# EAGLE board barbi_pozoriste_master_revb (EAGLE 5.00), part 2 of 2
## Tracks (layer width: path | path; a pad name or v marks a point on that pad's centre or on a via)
3.3  (via drill 0.6)
  Top 0.61: v8.89,36.67 9.37,37.15 10.48,37.15 11.11,37.15 11.81,36.45 15.62,36.45 15.83,36.24 Q1.1 15.88,36.32 | v-12.06,32.7 -12.06,27.46 -12.54,26.99 -12.54,21.27 -13.65,20.16 -33.18,20.16 -39.37,13.97 -39.37,-19.21 -35.56,-23.02 -33.02,-23.02 -29.05,-26.99 -28.89,-26.99 -24.45,-31.43 -24.29,-31.43 -20.95,-28.1 -20.95,-26.04 -20.92,-26 JP10.2
  Top 0.813: 10.48,37.15 R24.1
  Bottom 0.61: v8.89,36.67 -8.1,36.67 v-12.06,32.7
5V  (via drill 0.8 pad 1.27)
  Top 0.406: X11.A1 -1.8,-16.69 -7.33,-16.69 -8.58,-15.44 | 0.7,-15.83 1.59,-16.72 7.39,-16.72 X13.A1 9.96,-14.15 9.96,-12.31 11.28,-10.99 13.41,-10.99 X14.A1
  Top 0.61: X12.A1 -8.58,-15.44 | X11.A1 0.7,-14.25 0.7,-15.83 | v-29.63,-15.34 -29.57,-15.41 -17.97,-15.41 -17.77,-15.21 -17.77,-14.12 | -17.77,-14.12 -17.77,-14.09 | X10.A1 -17.77,-14.12
  Bottom 0.406: R65.2 -27.17,-17.71 | R64.2 -27.17,-15.54 | -17.86,-14.21 -17.86,-16.09 -17.28,-16.66 -9.49,-16.66 -8.45,-15.62
  Bottom 0.61: -27.17,-15.54 -27.37,-15.34 | -27.07,-15.34 -27.07,-15.45 R64.2 -27.08,-15.45 | R65.2 -27.07,-17.67 -27.08,-17.67 -27.08,-15.45 | -17.86,-14.21 X10.A1 | X12.A1 -8.45,-14.19 -8.45,-15.62 | -27.08,-15.45 -27.19,-15.34 v-29.63,-15.34
A0  (via drill 0.8 pad 1.27)
  Top 0.305: v-12.18,-22.75 -11.24,-21.81 -11.24,-17.56 -12.11,-16.69
  Top 0.406: -12.11,-16.69 -14.26,-16.69 -15.38,-15.57 -15.38,-14.2 X10.A2
  Bottom 0.406: JP7.1 -5.62,-25.92 | -8.74,-22.79 -8.79,-22.75 v-12.18,-22.75
  Bottom 0.61: -8.74,-22.79 JP7.1
A1
  Bottom 0.254: -0.89,-17.06 -0.89,-22.47
  Bottom 0.406: 2.78,-16.66 -0.45,-16.63 -0.89,-17.06
  Bottom 0.61: X11.A2 3.08,-14.31 3.08,-16.36 2.78,-16.66 | JP7.2 -3.15,-24.23 -0.89,-22.47
A2  (via drill 0.8 pad 1.02)
  Top 0.406: JP7.3 -1.89,-24.57 v-2.34,-21.75
  Bottom 0.254: v-2.34,-21.75 -1.89,-21.3 -1.89,-17.57
  Bottom 0.406: -1.89,-17.57 -2.77,-16.69 -5.18,-16.69 -6.14,-15.73 -6.14,-14.14 X12.A2
  Bottom 0.61: -6.01,-14.19 -6.07,-14.19 X12.A2
A3  (via drill 0.8 pad 1.27)
  Top 0.305: 7.62,-18.17 7.62,-21.38 6.93,-22.06 | 25.03,-22.04 v25.7,-22.71
  Top 0.406: 12.38,-16.02 11.69,-16.71 9.09,-16.71 7.62,-18.17 | 6.87,-22.13 3.8,-22.13 2.09,-23.84 2.09,-25.81 | 6.91,-22.04 25.03,-22.04
  Top 0.61: X13.A2 12.38,-14.23 12.38,-16.02 | 6.87,-22.13 6.93,-22.06 6.91,-22.04 | 2.09,-25.81 1.98,-25.81 JP7.4
  Bottom 0.61: R70.2 26.28,-22.71 v25.7,-22.71
A4  (via drill 0.8 pad 1.27)
  Top 0.305: v15.12,-23.57 | 4.44,-25.83 4.46,-25.83 JP7.5 | 4.7,-23.57 4.44,-23.82
  Top 0.406: v15.12,-23.57 4.7,-23.57 | 4.44,-23.82 4.44,-25.83
  Bottom 0.305: X14.A2 21,-16.09 21,-21.81 19.99,-22.82 15.92,-22.82 15.17,-23.57 v15.12,-23.57
  Bottom 0.406: 4.54,-25.8 4.54,-23.5 5.52,-22.52
  Bottom 0.61: JP7.5 4.54,-25.8 | 6.36,-22.52 6.39,-22.52 | 6.36,-22.52 R71.2 | 5.52,-22.52 6.36,-22.52
A5
  Bottom 0.305: X15.A1 21.77,-15.92 21.77,-22.67 20.66,-23.78 16.55,-23.78 14.89,-25.44 14.89,-26.31 13.77,-27.44 13.77,-27.45 13.7,-27.52 8,-27.52 6.87,-26.43 | 10.45,-22.49 10.45,-22.44 | 10.45,-22.49 R66.2 | 9.79,-24.05 10.45,-23.39 10.45,-22.49
  Bottom 0.406: JP7.6 8.82,-24.05 9.79,-24.05
  Bottom 0.61: JP7.6 7,-25.87 6.87,-25.87 6.87,-26.43
AC_NEUTRAL
  Top 1.676: -51.42,73.42 -51.42,72.97 -26.5,48.05 -11.95,48.05 | -11.95,48.05 -11.95,48.16 X1.B1 | X1.B2 -7.12,48.05 -11.95,48.05 | 63.08,63.54 62.86,63.76 61.51,63.76 55.34,69.94 55.34,70.16 55.22,70.05 | 84.86,-48.49 87.55,-42.65 84.86,-38.16 89.35,-27.84 95.19,-26.94 95.64,-22.9 96.31,-10.1 91.59,-6.73 92.27,5.17 98.55,10.55 94.29,21.11 | 20.58,95.39 25.59,92.95 27.61,91.83 28.96,86.44 40.18,81.95 44.22,85.09 49.39,82.62 | -84.42,49.39 -87.34,42.43 -83.52,39.07 -88.24,28.52 -89.54,27.21 -93.71,27.21 -99.07,21.85 -99.07,6.7 -95.35,2.98 -95.35,-4.3 -98.71,-7.66 -98.71,-18.81 -98.64,-18.88 -98.64,-22.02 -85,-35.67 -85,-38.04 -85.32,-38.16 -90.48,-45.12 -82.62,-56.12 | -48.05,-84.86 -42.66,-87.11 -38.62,-84.41 -28.74,-88.45 -26.05,-94.29 -21.11,-96.09 | 66,55.68 67.12,54.56 68.47,54.56 76.1,62.19 75.79,62.19 X6.B3
  Top 1.778: -84.42,49.39 -80.6,47.82 -72.07,50.97 -72.97,55.01 | -53.66,78.35 -51.87,76.56 -51.42,73.42 -55.46,69.38 -58.83,69.15 | -53.66,78.35 X2.B1 | X2.B3 -64.66,74.99 -58.83,69.15 | X2.B5 -65.78,62.19 -65.34,62.13 | -65.34,62.13 -62.64,61.74 -58.6,65.78 -58.83,69.15 | -72.97,55.01 X2.B7 | -72.97,55.01 -69.15,54.33 -65.11,58.37 -65.34,62.19 -65.34,62.13 | -82.85,-55.9 X3.B1 -82.62,-56.12 -76.11,-49.61 -74.54,-49.84 -69.6,-54.78 -69.6,-57.02 | -69.6,-57.02 X3.B3 | -63.09,-64.88 X3.B5 | -63.09,-64.88 -62.87,-61.51 -67.13,-57.25 -69.6,-57.02 | -56.13,-71.84 X3.B7 | -56.13,-71.84 -56.13,-68.7 -60.17,-64.66 -63.09,-64.88 | -56.13,-71.84 -53.44,-71.39 -47.38,-77.45 -48.05,-84.86 | -21.11,-96.09 14.36,-96.53 45.79,-83.51 52.53,-84.86 54.33,-83.06 X5.B1 54.77,-83.06 49.61,-77.9 49.16,-74.31 52.98,-70.49 56.11,-70.7 | X5.B3 56.35,-70.72 56.11,-70.7 | X5.B5 63.31,-63.76 62.62,-63.72 | 62.62,-63.72 59.49,-63.53 55.67,-67.35 56.12,-70.49 56.11,-70.7 | X5.B7 70.49,-56.57 68.92,-55 | 68.92,-55 62.63,-61.29 62.63,-63.53 62.62,-63.72 | X6.B5 63.08,63.54 62.41,59.27 66,55.68 | X1.B2 -6.78,48.27 | X1.B1 -12.17,47.82 | X6.B1 83.74,46.92 94.29,21.11 | 84.86,-48.49 75.43,-48.94 68.92,-55 | X6.B7 55.34,69.94 55.22,70.05 48.94,76.33 49.39,82.62 | 20.58,95.39 -17.14,95.84 -49.62,81.95 -50.07,81.95 -53.66,78.35
  Bottom 1.676: R89.2 30.46,53.44 36.81,53.44 46.92,63.54 49.61,63.54 61.73,51.41 65.33,51.41 75.65,61.74 75.65,62.19 | 75.65,62.19 | X6.B3 75.65,62.19
AC_PHASE
  Top 1.676: K5.2 42.91,37.46 33.22,47.15 33.22,52.99 31.2,55.01 28.96,55.01 R99.2 | R99.2 | R99.2 | K16.2 16.99,-64.28 29.94,-51.32 C1.1 33.9,-50.78 33.9,-43.33 K1.2 | -48.05,-33.67 -47.83,-33.9 K13.2 -41.99,-34.35 -41.99,-40.18 -28.46,-53.71 K14.2 -28.46,-61.24 | -48.05,-33.67 -61.3,-20.43 -65.78,-20.43 -66.01,-20.2 -66.16,-20.35 K12.2 | C14.1 -33.81,-66.58 -28.46,-61.24 | C13.1 -50.16,-35.78 -48.05,-33.67 | 51.31,31.31 51.86,32.56 | C5.1 51.31,31.31 | 51.31,31.31 64.36,18.26 K4.2 73.53,18.52 75.2,16.84 75.11,16.74 C4.1 75.2,16.52 75.2,9.66 72.51,6.96 72.51,6.06 72.96,5.62 72.96,0.96 K3.2 67.48,-4.62 72.51,-9.65 76.1,-9.65 C3.1 | C3.1 76.55,-9.2 | C3.1 76.46,-13.34 72.96,-16.84 72.51,-16.84 63.89,-25.45 K2.2 63.89,-26.63 70.27,-33 70.24,-33.02 C2.1 | -28.46,-61.24 -28.19,-61.51 -10.78,-61.51 -5.17,-67.12 | -5.17,-67.12 -5.17,-66.98 K15.2 -5.17,-66.89 -5.17,-66.68 -4.72,-66.68 -1.8,-63.76 16.19,-63.76 K16.2 | C15.1 -5.17,-70.77 -5.17,-67.12 | K16.2 17.06,-64.63 17.06,-73.11 C16.1 | C10.1 -68.25,36.66 -68.25,34.58 -62.87,29.19 | -62.87,29.19 -62.82,29.19 K10.2 -62.6,29.41 -52.31,29.41 -38.4,43.33 -37.5,43.33 | -62.87,29.19 -63.09,28.96 -63.09,11.45 -69.6,4.94 -69.6,4.52 | -69.6,4.52 -69.6,4.49 | -69.6,4.52 K11.2 -69.73,4.62 -74.22,9.11 C11.1 | C9.1 -37.72,50.42 -37.72,43.56 -37.5,43.33 | -37.5,43.33 K9.2 -35.57,41.4 | K8.2 -7.7,53.61 -5.58,53.61 -1.7,53.55 -1.7,48.3 -1.91,48.1 -1.98,48.17 X1.B3 | X1.B3 -1.77,48.41 -1.7,48.41 -1.34,48.04 3.07,48.04 3.07,48.15 X1.B4 | X1.B3 -2,48.17 -2,39.45 -2.15,39.3 -26.25,39.3 -26.27,39.31 -33.46,39.31 -35.55,41.4 -35.57,41.4 | -35.57,41.4 -35.62,41.4
  Top 1.778: K11.2 -69.38,4.72
  Top 1.93: K11.2 -69.59,4.72 -69.38,4.72 -62.42,-2.24 -62.42,-16.71 K12.2 -66.17,-20.43 -74.48,-20.43 C12.1
  Bottom 1.676: C3.1 76.64,-9.29 | K3.2 67.32,-4.52 | 10.77,60.62 13.91,60.62 15.94,58.6 20.43,58.6 23.34,55.68 R99.2 | R99.2 28.51,55.45 28.96,55.45 | R99.2 | R99.2 | K7.2 6.28,66.91 | -1.84,48.27 -1.92,48.19 X1.B3 | C5.1 52.08,32.33 50.07,30.32 K5.2 | R99.2 | R99.2 30.53,57.93 K6.2 30.53,60.62 32.78,60.62 C6.1 | K2.2 63.89,-25.45 | C7.1 6.28,70.58 K7.2 | 10.77,60.62 6.28,65.11 K7.2 | K8.2 -18.83,63.31 -18.86,63.31 -18.86,70.52 C8.1 | X1.B4 3,48.22 3,52.84 10.77,60.62
  Bottom 1.778: K12.2 -65.78,-20.43 | K15.2 -5.17,-67.12 | X1.B4 3.1,48.27 | X1.B4 | X1.B4
D2  (via drill 0.8)
  Top 0.61: 2.02,22.45 1.99,22.45 JP4.3 1.96,22.43 | 12.79,12.35 6.04,19.1 4.54,19.1 1.96,21.68 1.96,22.43 | 1.96,22.43 1.96,22.61
  Top 0.813: v12.79,-1.12 12.79,12.35
  Bottom 0.305: SV5.12 27.17,-4.52 23.73,-4.51
  Bottom 0.61: 23.73,-4.51 16.33,-4.61 13.58,-1.91 v12.79,-1.12
D3  (via drill 0.8)
  Top 0.406: -28.55,-2.18 -28.55,-2.23 SV2.12 | -21.62,5.28
  Top 0.813: -28.55,-2.18 -26.78,-1.73 -21.62,3.42 -21.62,5.28 -21.62,8.87 -15.43,15.06 -7.95,15.06 JP4.4 6.23,29.95 6.23,38.57 10.39,42.72 v10.39,43.91
  Bottom 0.406: 12.98,44.02 13.04,44.02 | 12.98,44.02 R55.1 | v10.39,43.91 10.51,44.02 12.98,44.02
  Bottom 1.676: R55.1 12.97,43.96 13.48,44.47 OK1.5
D4  (via drill 0.6)
  Top 0.406: -5.4,-30.8 -5.39,-30.8 C18.2 -5.08,-30.8 -5.11,-30.77 | -3.02,22.54 JP4.5
  Top 0.61: v-24.92,-28.73 -24.92,-28.26 -26.83,-26.35 -26.83,-25.24 -32.38,-19.68 -36.99,-19.68 -37.94,-18.73 -37.94,-18.57 | -5.11,-30.77 U$2.1
  Top 0.813: v-20.48,-33.18 -20.48,-38.1 -15.72,-42.86 -5.4,-42.86 0,-37.78 0,-31.91 -1.11,-30.8 R23.1 -5.08,-30.8 | -37.94,-18.57 -37.94,13.18 -32.23,18.89 -6.67,18.89 JP4.5 | -5.08,-30.8 -5.11,-30.77 | -5.08,-30.8 C18.2
  Bottom 0.406: -3.19,22.41 JP4.5 | -12.35,5.17 -12.38,5.2 SV3.5
  Bottom 0.61: -14.82,10.78 -14.82,7.63 -12.38,5.2
  Bottom 0.813: -14.82,10.78 -3.19,22.41 | v-24.92,-28.73 v-20.48,-33.18
D5
  Bottom 0.305: -12.38,2.89 -12.35,2.92 | -12.38,2.89 SV3.7 | -14.15,2.47 -12.8,2.47 -12.38,2.89
  Bottom 0.406: -5.68,21.71 JP4.6
  Bottom 0.61: -5.68,21.71 -16.39,11 -16.39,4.72 -14.15,2.47
D6  (1 unrouted)
  Bottom 0.305: -28.44,2.84 -28.29,2.7
  Bottom 0.61: JP4.7 -8.18,22.45 -8.09,22.45 -8.09,21.55 -11.68,17.96 -14.37,17.96 -26.05,6.29 -26.27,4.72 -27.62,3.37 -28.52,2.92 -28.52,2.89 SV2.8
D7
  Bottom 0.61: SV2.6 -13.96,19.98 -12.8,19.98 -11.01,21.78 -11.01,22.23 -10.94,22.23 JP4.8
D8
  Bottom 0.406: -28.41,7.97 -28.51,7.97 SV2.4
  Bottom 0.61: JP3.1 -14.82,22.16 -14.82,21.55 -28.29,8.08 -28.72,8.08 | -28.72,8.08 -28.74,8.08 | -28.72,8.08 SV2.4
D9
  Bottom 0.305: -28.56,10.51 SV2.2
  Bottom 0.61: -16.84,22.23 -28.56,10.51
  Bottom 0.813: JP3.2 -17.07,22.45 -16.84,22.23
D10
  Bottom 0.305: JP3.3 -19.81,22.41
  Bottom 0.406: -31.12,10.46 SV2.1 -30.99,10.35 | -30.99,10.35 -30.99,10.33 | -30.99,11.23 -30.99,10.35
  Bottom 0.61: -31.12,10.46 -31.21,10.55 | -19.81,22.41 -30.99,11.23
D11
  Bottom 0.305: JP3.4 -22.19,22.27
  Bottom 0.406: SV2.3 -31.15,7.92 -31.21,7.86 -31.66,7.86
  Bottom 0.61: -22.19,22.27 -33.23,11.23 -33.23,9.43 -31.66,7.86
D12
  Bottom 0.305: JP3.5 -24.73,22.42 -24.7,22.45 -24.7,21.55
  Bottom 0.406: -31.43,5.38 SV2.5
  Bottom 0.61: -24.7,21.55 -34.58,11.68 -34.58,8.53 -31.43,5.38
D13
  Bottom 0.305: -31.1,2.81 -30.99,2.7 | -31.1,2.81 SV2.7 | -31.1,2.81 -31.21,2.92 -31.44,3.15
  Bottom 0.406: -31.21,2.92 -31.13,2.84 SV2.7
  Bottom 0.61: -31.21,2.92 -35.93,7.63 -35.93,12.13 -27.27,20.78 JP3.6 -27.17,22.51
D14
  Top 0.61: R18.1 9.05,26.73 11.45,24.33 11.45,22.6 11.48,22.58 11.46,22.56 JP5.1
  Top 0.813: JP5.1 11.43,22.38 | JP5.1 | JP5.1 11.59,22.54
  Bottom 0.406: JP5.1 11.46,21.15 10.16,19.84 7.62,19.84 -1.91,10.32 -9.68,10.32 -9.84,10.16 -9.85,10.16 SV3.2
D15
  Top 0.406: 21.91,29.65 21.9,35.75 21.9,35.76 19.3,38.35 16.89,38.35 16.81,38.44 | 16.81,38.44 16.76,38.48 | 16.81,38.44 Q1.3
  Top 0.61: 21.91,29.65 21.91,28 20.7,26.8 15.75,26.8 13.97,25.02 13.97,22.48 14,22.45 JP5.2 | R25.2 12.77,38.16 13.34,37.72 16.26,37.72 16.89,38.35 16.83,38.42 Q1.3
  Bottom 0.305: -9.85,7.67 -9.88,7.63 | SV3.4 -9.85,7.67 | -9.85,7.67 -9.66,7.86
  Bottom 0.406: JP5.2 14,19.85 13.02,18.86 8.08,18.86 -2.7,8.08 -9.66,7.86
D16
  Top 0.61: JP1.2 26.06,29.6 26.06,27.97 23.75,25.65 17.02,25.65 16.51,25.15 16.51,22.23 16.54,22.26 JP5.3
  Bottom 0.305: -10.03,5.24 -10.11,5.17 | SV3.6 -10.03,5.24 | -10.03,5.24 -9.43,5.84
  Bottom 0.406: JP5.3 16.54,20.59 13.69,17.74 8.3,17.74 -3.6,5.84 -9.43,5.84
D17
  Top 0.61: JP1.3 28.6,29.89 28.6,28.73 24.38,24.51 19.18,24.51 19.05,24.38 19.05,22.7 19.21,22.54 JP5.4
  Bottom 0.305: -9.66,2.92 -9.4,2.73 SV3.8
  Bottom 0.406: JP5.4 19.31,18.87 17.26,16.82 8.77,16.82 8.75,16.84 -5.17,2.92 -9.66,2.92
D18
  Bottom 0.305: 8.04,1.38 8.08,1.35 | SV4.7 8.04,1.38 | 2.69,9.43 2.91,6.51 8.04,1.38
  Bottom 0.406: JP5.5 21.62,19.39 17.51,15.27 8.75,15.49 2.69,9.43
D19
  Bottom 0.305: SV4.5 8.04,4.08
  Bottom 0.406: JP5.6 24.16,20.13 18.18,14.15 8.75,14.15 3.81,9.21 4.04,8.08 8.04,4.08
D22
  Bottom 0.305: 10.59,9.17 10.55,9.21 | SV4.2 10.59,9.17 | 10.59,9.17 11,8.76
  Bottom 0.406: 11,8.76 17.73,8.76 26.3,17.33 26.38,17.33 28.89,19.84 37.47,19.84 37.62,20 37.66,19.97 JP9.16
D24
  Bottom 0.406: JP9.15 27.8,17.33 16.99,6.51 10.48,6.51 10.47,6.51 | 10.47,6.51 10.32,6.35 | SV4.4 10.47,6.51
D26
  Bottom 0.305: 10.59,4.23 10.55,4.27 | SV4.6 10.59,4.23 | 10.59,4.23 11.22,3.59
  Bottom 0.406: 11.22,3.59 15.71,3.59 26.49,14.82 37.52,14.82 37.62,14.92 37.66,14.89 JP9.14
D28
  Bottom 0.305: SV4.8 16.24,1.43 20.65,5.84 20.65,7.19
  Bottom 0.406: 20.65,7.19 27.16,13.7 34.72,13.7 36.2,12.22 37.62,12.22 37.65,12.25 JP9.13
D30
  Bottom 0.305: SV5.1 25.82,9.21
  Bottom 0.406: 25.82,9.21 25.81,9.22 25.81,10.11 28.28,12.57 33.62,12.57 36.51,9.68 37.69,9.68 | 37.69,9.68 JP9.12 | 37.69,9.68 37.72,9.65
D31
  Bottom 0.406: JP8.12 41.77,9.71 42.86,10.79 42.86,15.56 45.4,18.1 52.23,18.1 52.39,17.94 SV7.1
D32
  Bottom 0.406: 28.34,9.43 28.28,9.43 | SV5.2 28.34,9.43 | 28.34,9.43 34.7,9.43 36.99,7.14 37.62,7.14 37.65,7.17 JP9.11
D33
  Bottom 0.406: SV7.2 54.86,18.03 53.66,16.83 45.88,16.83 43.97,14.92 43.97,9.68 41.43,7.14 40.32,7.14 40.34,7.17 JP8.11
D34
  Bottom 0.254: 30.08,8.08 29.95,8.21 27.13,8.21 25.92,7 25.79,7 25.79,6.94 SV5.3
  Bottom 0.305: SV5.3 25.82,6.97
  Bottom 0.406: 30.08,8.08 33.51,8.08 36.99,4.6 37.62,4.6 37.65,4.63 JP9.10
D35
  Bottom 0.406: SV7.3 46.29,15.49 45.09,14.29 45.09,8.26 41.59,4.76 40.64,4.76 40.36,4.48 | 40.36,4.48 40.32,4.45 | JP8.10 40.36,4.48
D36
  Bottom 0.406: SV5.4 28.37,6.92 28.37,6.96 32.09,6.96 36.99,2.06 37.62,2.06 37.65,2.09 JP9.9
D37
  Bottom 0.406: SV7.4 54.7,15.49 53.5,14.29 46.99,14.29 46.35,13.65 46.35,7.46 40.96,2.06 40.32,2.06 40.34,2.09 JP8.9
D38
  Bottom 0.254: 30,5.53 29.91,5.62 26.6,5.62 25.89,4.91 25.89,4.35 25.84,4.35 SV5.5
  Bottom 0.305: SV5.5 25.92,4.37
  Bottom 0.406: 30,5.53 31.62,5.53 37.62,-0.48 37.65,-0.45 JP9.8
D39
  Bottom 0.406: SV7.5 48.51,12.95 47.47,11.91 47.47,6.03 40.96,-0.48 40.48,-0.48 40.36,-0.6 | 40.36,-0.6 40.32,-0.64 | JP8.8 40.36,-0.6
D40
  Bottom 0.406: JP9.7 37.49,-2.99 37.47,-3.02 30.08,4.37 SV5.6
D41
  Bottom 0.406: SV7.6 55.03,12.8 53.98,11.75 49.53,11.75 48.58,10.79 48.58,3.81 41.75,-3.02 40.32,-3.02 | 40.32,-3.02 40.35,-2.99 JP8.7 | 40.32,-3.02 40.16,-3.17
D42
  Bottom 0.254: SV5.7 25.82,2.01 26.99,3.17 29.69,3.17 30.16,2.7
  Bottom 0.305: SV5.7 25.82,2.03
  Bottom 0.406: JP9.6 37.65,-5.53 37.62,-5.56 30.16,1.91 30.16,2.7
D43
  Bottom 0.406: SV7.7 50.42,10.41 49.85,9.84 49.85,2.86 41.43,-5.56 40.64,-5.56 40.48,-5.4 JP8.6
D44
  Bottom 0.406: SV5.8 28.49,1.83 33.66,-3.33 33.66,-4.13 37.62,-8.1 37.65,-8.07 JP9.5
D45
  Bottom 0.406: JP8.5 41.3,-8.07 50.8,1.43 50.8,8.1 51.59,9.21 53.82,9.21 55.03,10.42 | 55.03,10.42 55.09,10.48 | 55.03,10.42 SV7.8
D46
  Bottom 0.254: JP9.4 38.91,-9.34 42.4,-9.34 43.5,-8.26 44.61,-8.26 44.63,-8.28 44.7,-8.28
  Bottom 0.305: 44.7,-8.28 SV6.1
D47
  Bottom 0.406: JP8.4 43.2,-10.61 44.29,-9.53 53.82,-9.53 55.06,-8.28 | 55.06,-8.28 55.09,-8.26 | 55.06,-8.28 SV6.2
D48
  Bottom 0.254: JP9.3 37.81,-13.15 39.06,-11.87 44.14,-11.87 45.27,-10.77 45.34,-10.77
  Bottom 0.305: SV6.3 52.5,-10.81 52.53,-10.77 45.34,-10.77
D49
  Bottom 0.254: 45.57,-11.9 44.31,-13.15 JP8.3
  Bottom 0.305: SV6.4 55.04,-10.59 55.22,-10.77 53.88,-12.12 45.57,-11.9
D50
  Bottom 0.254: JP9.2 38.92,-14.41 44.8,-14.41 46.02,-13.2 | 46.02,-13.2 46.04,-13.18 | 46.02,-13.2 46.02,-13.24
  Bottom 0.305: SV6.5 52.42,-13.36 52.3,-13.24 46.02,-13.24
D51
  Bottom 0.254: 46.51,-14.59 46.51,-14.61 45.42,-15.69 JP8.2
  Bottom 0.305: SV6.6 55.04,-13.28 55,-13.24 53.65,-14.59 46.51,-14.59 46.47,-14.59
D52
  Bottom 0.254: JP9.1 37.81,-18.23 39.05,-16.97 45.88,-16.94 46.99,-15.88 52.39,-15.88 52.5,-15.98 | 52.5,-15.98 52.55,-16.03 | 52.5,-15.98 SV6.7
D53
  Bottom 0.254: 47.37,-17.29 47.33,-17.29 46.38,-18.23 JP8.1
  Bottom 0.305: 55.22,-15.71 SV6.8 53.65,-17.29 47.37,-17.29
GND  (via drill 0.6, 0.8, 0.9 pad 1.27, 1.3 pad 1.93, 1.4)
  Top 0.305: -13.14,-25.69 -10.12,-22.68 -10.12,-21.29 -10.12,-16.62 -12.73,-14.01
  Top 0.406: 7.85,-6.06 7.91,-6.06 SV4.13 | K13.4 -35.18,-41.01 -35.18,-40.88 -30.86,-40.88 JP10.4 | X10.A3 -12.82,-14.17 -12.82,-14.01 -12.73,-14.01 | -29.86,22.35 -29.86,22.23 | -29.86,22.35 JP3.7 | -29.86,22.68 -29.86,22.35 | C19.1 | C19.1 | C19.1 R22.1 -12.38,-33.81 -12.06,-33.5 -12.06,-32.86 -11.27,-32.07 -10.32,-32.07 -9.68,-31.43 -9.68,-30.96 | -9.68,-30.96 | -9.68,-30.96 U$2.2 -9.75,-30.77 -9.78,-30.73 -9.78,-29.08 | U$1.1 1.97,-30.29 0,-28.32 -9.02,-28.32 -9.78,-29.08 | JP10.5 -13.3,-26.2 -11.05,-28.45 -10.41,-28.45 -9.78,-29.08 | 15.24,30.99 | JP2.1 15.24,30.99 | R19.2 15.21,30.96 15.24,30.99 | -10.12,-21.29
  Top 0.61: v-22.78,-10.73 -22.55,-11.75 -12.54,-11.75 | -12.54,-11.75 -12.39,-11.75 -12.37,-11.72 -12.34,-11.72 -12.34,-4.96 SV3.13 | -13.14,-25.69 JP10.5 | -12.54,-11.75 | -12.54,-11.75 -12.54,-14 | 7.46,-6.78 SV4.13 7.46,-6.78 | 7.46,-6.78 7.46,-12.24 5.88,-13.82 5.88,-14.01 X11.A3 | 7.46,-6.78 7.46,-7.97 7.47,-7.96 24.4,-7.96 | 25.94,-5.67 25.94,-5.65 | 25.94,-5.67 SV5.13 | 24.4,-7.96 25.94,-6.42 25.94,-5.67 | X15.A2 26,-14.19 26,-9.55 24.4,-7.96 | K3.4 65.81,5.64 63.34,3.17 63.34,-11.91 67.64,-16.2 K2.4 | 48.94,-29.63 48.94,-29.64 48.9,-29.69 52.32,-33.11 LSP3.MP | K12.4 -64.78,-29.83 -68.74,-25.88 v-68.74,-22.86 | -59.05,0.25 -58.98,0.25
  Top 0.813: SV6.13 52.64,-23.66 | 48.94,-29.63 44.45,-29.63 K1.4 | SV7.13 49.5,-0.2 49.5,-22.11 50.96,-23.57 52.53,-23.57 | K9.4 -40.67,32.13 -39.29,30.76 -37.95,30.76 -29.86,22.68 | K15.4 5.16,-67.06 5.16,-72.06 | 5.16,-72.06 10.32,-77.23 18.85,-77.23 26.49,-69.59 26.49,-60.61 26.42,-60.61 K16.4 | LSP2.MP -12.58,-68.22 -12.58,-72.29 -14.37,-74.08 -14.37,-76.33 -11.01,-79.7 -2.48,-79.7 5.16,-72.06 | v77.48,18.69 77.4,18.69 68.69,27.39 61.96,27.39 61.28,28.07 61.14,27.92 K4.4
  Top 1.016: LSP7.MP -58.98,0.25 -58.96,2.06 v-63.09,6.06 | K4.4 43.25,45.8 v38.16,45.8 | K7.4 -3.6,66.83 -3.6,63.54 | -3.6,63.54 -3.6,61.07 -0.23,57.7 -0.23,57.25 LSP5.MP 3.59,57.48 13.91,47.15 17.06,47.15 OK1.4 | -3.6,63.54 | -3.6,63.54 v12.34,63.54 | v-41.4,0.25 -59.05,0.25 | LSP1.MP -20.79,-3.9 -22.61,-5.71 -22.61,-10.67 -22.73,-10.79 -22.78,-10.75 v-22.78,-10.73
  Top 1.27: v-29,36.47 -36.33,36.47 -38.89,33.91 -40.67,32.13 | K8.4 -28.1,57.34 -25.14,54.38 -21.97,54.38 -22.01,54.34 LSP6.MP
  Top 1.422: -40.67,32.13 | -38.89,33.91
  Bottom 0.305: 7.92,-15.75 7.92,-22.18
  Bottom 0.406: SV2.13 -31.1,-4.82 | 6.33,-14.17 7.92,-15.75 | JP10.5 -13.33,-25.83 -13.33,-25.72 -15.7,-25.72 JP10.4 | R70.1 34.21,-18.33 36.67,-20.8 37.31,-20.8 37.47,-20.64 37.49,-20.66 JP11.1 37.44,-20.77 | 37.44,-20.77 JP11.2 | 37.44,-20.77 37.31,-20.64 | 23.57,32.38 23.57,32.43 22.73,33.27 17.53,33.27 15.24,30.99 | 23.57,32.38 JP1.1 | 15.24,30.99 | 15.24,30.99 JP2.1 | 23.57,32.38 23.62,32.38 25.11,33.87 25.11,35.11
  Bottom 0.61: -36.05,-13.1 -35.99,-13.1 S1.1 -35.85,-13.06 -29.53,-13.06 S1.2 -29.31,-13.02 -27.53,-13.02 LED33.C -26.86,-13.48 -26.86,-11.87 -26.13,-11.14 -25.52,-10.62 -23.71,-10.65 v-22.78,-10.73 | -31.18,-4.63 -31.18,-4.7 SV2.13 | 7.92,-22.18 R71.1 | X11.A3 5.69,-14.2 5.69,-14.17 6.33,-14.17 | 25.98,-14.21 25.98,-14.17 | X15.A2 25.98,-14.21 | R70.1 25.98,-15.55 25.98,-14.21 | JP11.2 48.24,-20.77 51.12,-23.65 52.55,-23.65 52.68,-23.52 | 52.68,-23.52 52.7,-23.5 | 52.68,-23.52 SV6.13 | SV7.13 52.49,1.64 56.52,-2.38 56.52,-5.08 67.64,-16.2 K2.4 | OK1.4 18.55,47.01 19.84,45.72 19.84,41.91 23.81,37.94 23.81,37.47 25.11,36.17 | 25.11,36.17 C99.- | 25.11,36.17 25.11,35.11 | v-68.74,-22.86 -68.74,-20 -66.2,-17.46 -66.04,-17.46 -59.05,-10.48 -59.05,-8.26 -59.05,-8.1 LSP7.MP | -29.84,22.35 -29.81,22.39 JP3.7
  Bottom 0.813: v-63.09,6.06 -63.32,6.29 -63.32,16.62 -66.68,19.98 -66.66,19.98 K10.4 | K3.4 71.43,5.64 75.46,1.62 75.68,1.62 80.56,6.5 80.56,15.61 v77.48,18.69
  Bottom 1.016: C99.- 25.6,35.81 28.06,35.81 | 28.06,35.81 34.01,35.81 35.8,37.61 35.8,37.58 K5.4 | -36.05,-11.3 -36.05,-13.1 | -36.05,-11.3 -31.18,-6.43 -31.18,-4.7 | v38.16,45.8 33.67,45.8 28.06,40.19 28.06,35.81 | K7.4 -16.66,54.33 LSP6.MP | K6.4 20.11,63.54 v12.34,63.54 | -36.05,-11.3 -36.05,-2.3 -38.61,0.25 | -38.61,0.25 -38.61,11.94 -29.84,20.7 -29.84,22.35 | -38.61,0.25 v-41.4,0.25 | LSP7.MP -59.05,-8.26 -61.77,-5.54 K11.4
  Bottom 1.27: v-29,36.47 -23.12,42.35 -23.12,53.34 -22.03,54.44 -22.01,54.42 LSP6.MP
  pour Bottom (isolate 1.676, hatched): -47.38,46.03 -49.4,14.82 arc-90 44,16.62 60.84,31.66 arc-90 50.96,-50.06 arc-90 -50.07,-50.06 -52.31,-47.82 arc-90 -52.99,43.56 -48.5,46.7 arc-90
  pour Top (isolate 1.422, hatched): -47.6,46.25 -49.4,14.82 arc-90 43.77,16.39 61.06,31.88 arc-90 49.84,-50.29 arc-90 -51.19,-50.29 -53.44,-48.04 arc-90 -53.44,42.66 -49.62,46.48 arc-90
INPUT1
  Bottom 0.61: 37.96,-39.73 37.97,-39.75 | R119.1 37.96,-39.73 | 32.32,-38.84 37.06,-38.84 37.96,-39.73
  Bottom 0.813: SV1.2 -52.54,5.98 -52.54,-0.22 -45.24,-7.07 -45.24,-15.6 -36.6,-24.24 -36.6,-32.55 -9.1,-60.05 9.98,-60.05 31.2,-38.84 32.32,-38.84 | R119.1 37.9,-39.73
INPUT2
  Bottom 0.61: 67.18,-24.13 67.19,-24.14 67.23,-24.14 | 66.34,-24.13 67.18,-24.13 | R112.1 68.42,-22.9 67.18,-24.13
  Bottom 0.813: SV1.1 -43.67,1.64 -43.67,-14.93 -35.25,-23.35 | -8.54,-57.92 9.42,-57.92 30.53,-36.82 33.67,-36.82 37.04,-33.45 37.04,-30.31 39.28,-28.06 55.22,-28.06 60.39,-22.9 65.1,-22.9 66.34,-24.13 | -8.54,-57.92 -8.76,-57.92 | 67.23,-24.14 67.23,-24.13 | -35.25,-23.35 | -35.25,-23.35 -25.37,-33.23 -25.37,-41.08 -8.54,-57.92
INPUT3
  Bottom 0.305: SV1.4 -50.23,8.2 -44.79,8.2
  Bottom 0.406: -44.79,8.2 -39.29,13.7 -39.29,19.31 -32.78,25.82 39.45,25.82 42.37,22.9
  Bottom 0.61: 42.46,22.9 42.37,22.9 43.55,22.9 43.66,23.01 59.15,23.01 62.97,19.2 62.97,16.28 64.65,14.6 64.65,1.13 66.17,-0.38 69.98,-0.38 70.01,-0.35 70.01,-0.32
  Bottom 0.813: R113.1 69.95,1.49 70.01,1.43 70.01,-0.32
INPUT4
  Bottom 0.406: -48.92,9.43 -46.03,9.43 -40.64,14.82 -40.64,19.31 -33.79,26.16 -33.81,26.17 | 45.54,24.7 43.3,26.94 -32.78,26.94 -32.8,26.92 -33.04,26.92 -33.79,26.17 -33.81,26.17 | -33.81,26.17 -33.82,26.17
  Bottom 0.61: 45.54,24.7 60.27,24.7 61.47,23.5 63.12,23.5 64.9,25.27 64.88,25.29 R114.1
  Bottom 0.813: -48.92,9.43 SV1.3 | 64.77,25.08 64.86,25.18 R114.1
INPUT5
  Bottom 0.305: SV1.6 -50.27,10.78 -46.7,10.78
  Bottom 0.406: -41.76,15.72 | -41.76,15.72 -46.7,10.78 | -41.76,15.72 -41.76,19.76 -33.23,28.29 37.94,28.29 40.13,30.48 40.13,36.58 40.16,36.54 R115.1
INPUT6  (via drill 0.8)
  Top 0.61: v26.94,60.84 26.71,60.4 26.49,60.62 4.04,60.62 v3.92,60.73
  Bottom 0.406: -48.97,12.01 -47.26,12.01 -43.11,16.17 -43.11,20.21 -34.13,29.19 -30.81,29.19 -16.66,43.33 -16.66,48.74 -4.72,60.84
  Bottom 0.61: -48.97,12.01 SV1.5 | v3.92,60.73 3.81,60.84 -4.72,60.84
  Bottom 0.813: R116.1 26.19,64.93 26.94,64.19 v26.94,60.84
INPUT7
  Bottom 0.305: SV1.8 -50.31,13.36 -47.71,13.36
  Bottom 0.406: -2.48,64.77 -2.48,64.89 -17.78,49.42 -17.78,44.01 -31.48,30.31 -34.58,30.31 -44.12,20.77 -44.34,16.5 -47.47,13.38 -47.71,13.38 -47.71,13.36 | -2.48,64.77
  Bottom 0.61: -2.81,64.77 -2.48,64.77 0.89,64.77 1.65,65.53 1.65,68.07 0.14,69.58 | 0.14,69.58 0.13,69.6 | 0.14,69.58 R117.1
INPUT8
  Bottom 0.61: -49.17,14.6 SV1.7 -48.72,14.6 -46.48,16.84 -46.72,23.36 -27.86,42.22 -27.62,55.9 -27.62,55.95 -23.24,60.33 -23.24,61.72 -24.66,63.14 R118.1
INPUT9
  Bottom 0.813: SV8.2 -57.25,1.51 -57.25,26.27 -57.17,26.27 -43.94,39.5 -42.55,39.5 -41.77,38.72 R91.1 -41.77,38.59 -41.75,38.58
INPUT10
  Bottom 0.61: SV8.1 -59.05,0.76 -59.05,24.02 -61.97,26.94 -64.21,26.94 -64.24,26.94 -64.26,26.92 -65.15,26.92 -67.46,24.61 R101.1
INPUT11  (1 unrouted)
  Bottom 0.305: -52.76,-7.86 -52.54,-8.08 -49.84,-8.08 -48.95,-8.98 SV8.4 -48.95,-9.43
  Bottom 0.61: -52.76,-7.86 -62.42,1.8 | R111.1 -71.62,-1.07 | -71.4,-0.75 -71.4,0.61 -70.23,1.78 -62.36,1.78 -62.38,1.76
  Bottom 0.813: R111.1 -71.85,-1.2 -71.4,-0.75
INPUT12
  Bottom 0.61: R121.1 -65.9,-27.06 -67.13,-25.83 -67.13,-24.94
  Bottom 0.813: SV8.3 -51.57,-9.43 -52.54,-9.43 -67.13,-24.02 -67.13,-24.94
  Bottom 1.016: R121.1 -65.86,-27.09
INPUT13  (via drill 0.8)
  Top 0.813: SV8.6 -48.93,-11.9 -45.58,-15.23 -39.29,-21.52 v-39.29,-37.04
  Bottom 0.813: v-39.29,-37.04 -39.32,-37.04 -39.37,-36.99 -39.74,-37.36 R131.1
INPUT14  (via drill 0.8)
  Top 0.813: v-62.19,-23.57 -54.34,-31.43 -54.34,-35.92 -35.93,-54.33 v-33.68,-54.33
  Bottom 0.813: SV8.5 -62.19,-22.59 v-62.19,-23.57 | v-33.68,-54.33 -30.99,-54.33 -26.27,-59.04 -26.27,-62.63 -26.95,-64.23 -26.26,-64.55 -25.52,-64.81 -25.45,-64.81 R141.1
INPUT15  (via drill 0.8)
  Top 0.813: v-5.17,-63.98 -5.17,-62.19 -9.66,-57.7 -11.01,-57.7 v-12.46,-59.16
  Bottom 0.813: v-5.17,-63.98 -2.7,-66.45 -2.7,-69.26 0.68,-69.26 0.79,-69.37 0.8,-69.37 151.1 | SV8.8 -38.71,-24.66 -38.71,-32.47 -12.54,-58.64 -12.54,-59.14 -12.48,-59.14 v-12.46,-59.16
  Bottom 1.016: 1.12,-69.37 | 151.1 1.12,-69.37 | 1.12,-69.37 1.08,-69.33
INPUT16
  Bottom 0.813: SV8.7 -58.6,-21.53 -58.6,-24.02 -55.23,-27.39 -45.92,-27.27 -27.62,-45.57 | -27.62,-45.8 -27.84,-54.78 -20.43,-62.19 18.63,-62.19 19.75,-63.31 19.75,-65.11 20.43,-65.78 | -27.62,-45.8 -27.62,-45.57 | 20.43,-65.78 20.43,-65.93 | -27.62,-45.8 -27.62,-45.57 | -27.62,-45.8 | R161.1 22.84,-64.71 22.08,-65.47 22.08,-65.42 22.07,-65.41 21.69,-65.78 20.43,-65.78
LAMP1
  Bottom 1.676: F1.1 57.69,-48.72 53.2,-48.72 L1.2
LAMP2
  Bottom 1.676: F2.1 90.47,-22.8 90.47,-22.67 84.33,-22.67 L2.2
LAMP3
  Bottom 1.676: 83.8,-10.1 83.74,-10.1 | L3.2 83.8,-10.1 | F3.1 88.41,-10.1 83.8,-10.1
LAMP4
  Bottom 1.676: 81.57,18.26 81.49,18.19 | L4.2 81.57,18.26 | F4.1 82.79,19.48 81.57,18.26
LAMP5
  Bottom 1.676: 47.47,57.36 47.59,57.48 | 47.47,57.36 F5.1 | L5.2 45.15,55.04 47.47,57.36
LAMP6
  Bottom 1.676: F6.1 23.6,88.26 23.57,88.23 23.57,80.89 25.19,79.26 25.11,79.17 L6.2
LAMP7
  Bottom 1.676: -9.66,90.37 -9.66,90.48 | -9.66,90.37 F7.1 | -5.39,82.17 -9.66,86.44 -9.66,90.37
  Bottom 1.778: L7.2 -5.39,82.17
LAMP8
  Bottom 1.676: -35.54,73.26 -35.48,73.19 | -35.54,73.26 L8.2 | F8.1 -40.79,78.51 -35.54,73.26
  Bottom 1.778: L8.2 -35.7,73.42
LAMP9
  Bottom 1.676: F9.1 -53.56,45.48 L9.2
LAMP10
  Bottom 1.676: -81.5,24.47 -81.49,24.46 L10.2 -81.55,24.25 -88.46,24.25 -90.03,22.68
  Bottom 1.778: -90.03,22.68 F10.1
LAMP11
  Bottom 1.676: L11.2 -85.17,-7.33 -85.09,-7.41 -87.07,-9.38 F11.1
  Bottom 1.778: L11.2 -85.09,-7.41
LAMP12
  Bottom 1.676: L12.2 -76.17,-37.44 -76.11,-37.49 -80.62,-42 F12.1
LAMP13
  Bottom 1.676: L13.2 -56.58,-39.96 -62.07,-45.45 F13.1
LAMP14
  Bottom 1.676: L14.2 -40.13,-73.86 -40.19,-73.86 -40.19,-78.16 F14.1
LAMP15
  Bottom 1.676: F15.1 -12.8,-90.51 -12.8,-84.19 -11.23,-82.62
  Bottom 1.778: L15.2 -11.23,-82.62
LAMP16
  Bottom 1.676: F16.1 19.52,-88.23 19.53,-88.23 19.53,-83.74 16.83,-81.04
  Bottom 1.778: L16.2 16.83,-81.04
N$1
  Bottom 1.676: K2.1 62.16,-30.29 62.18,-30.31 59.49,-33 59.49,-36.59 64.65,-41.76 70.74,-41.76 73.5,-38.99 | L2.1 76.3,-36.2 73.5,-38.99 | R2.2 73.5,-38.99
N$2
  Bottom 1.676: K1.1 29.18,-45.8 29.18,-50.74 35.69,-57.25 L1.1 38.39,-52.31 48.71,-41.98 52.75,-41.98 R1.1
N$3
  Bottom 1.676: C1.2 45.03,-34.44 R1.2
N$4
  Bottom 1.676: R2.1 63.82,-33.61 64.14,-33.61 64.2,-33.67 75.98,-21.9 75.98,-19.21 | 75.98,-19.21 76.1,-19.08 | 75.98,-19.21 C2.2
N$5
  Bottom 1.676: 86.47,37.5 90.27,34.85 99.37,9.66 94.5,7.15 94.39,-6 99.57,-9.56 98.56,-19.91 | 98.56,-19.91 98.33,-24.47 | 98.56,-19.91 98.78,-23.35 95.69,-30.05 90.3,-30.07 86.54,-39.22 90.56,-43.4 84.63,-52.27 79.52,-58.56 X5.B8
  Bottom 1.778: 86.47,37.5 F4.2 | X5.B8 79.69,-58.59
N$6
  Bottom 1.676: 83.65,6.42 83.51,6.29 83.27,6.53 R3.2 | K3.1 67.52,-9.6 67.57,-9.65 83.65,6.42 | 83.65,6.42 L3.1
N$7
  Bottom 1.016: OK1.1 24.52,41.93 24.47,41.98 23.12,41.98 22,43.11 22,48.95 21.32,49.62 15.94,49.62 13.91,51.64 13.91,53.88 15.71,55.68 | 15.71,55.68 | 15.71,55.68 R99.1
  Bottom 1.676: 24.91,41.98 24.86,41.93 OK1.1
N$8
  Bottom 1.676: C3.2 71.67,10.5 R3.1
N$9
  Bottom 1.778: F1.2 43.55,-64.66 X5.B2
N$10
  Bottom 1.676: 72.73,-44.45 72.6,-44.45 58.37,-58.68 58.37,-65.59 65.33,-72.54 | 65.33,-72.54 65.34,-72.56 | 65.33,-72.54 X5.B4
  Bottom 1.778: 81.94,-43.33 F2.2 81.72,-43.55 72.73,-44.45
N$11
  Bottom 1.676: C4.2 69.22,30.46 67.27,32.41 R4.1
N$12
  Bottom 1.676: R4.2 72.37,36.29 75.2,33.45 75.27,33.52 L4.1 75.29,33.54 75.43,33.68 75.65,33.45 75.65,23.57 66.97,14.9 K4.1
N$13
  Bottom 1.676: R5.2 40.35,48.55 52.53,36.37 56.12,36.37 56.57,36.82 56.63,36.76 L5.1 56.83,36.63 56.35,36.15 56.35,32.56 50.52,26.73 K5.1
N$14
  Bottom 1.27: 29.45,45.58 29.46,45.59 | 29.45,45.58 29.41,45.58 | OK1.2 28.33,44.46 29.45,45.58
  Bottom 1.676: R89.1 24.91,52.31 29.41,47.82 29.41,45.58 | OK1.2
N$15
  Bottom 1.676: R5.1 31.58,39.67 33.22,41.31 39.51,41.31 41.3,43.11 C5.2
N$16
  Bottom 1.676: 90.92,10.11 90.92,-7.41 96.31,-11 95.97,-15.6 94.96,-24.02 93.61,-26.96 87.78,-26.71 83.29,-37.94 82.66,-39.62 86.91,-43.93 83.61,-48.35 80.93,-47.93 76.33,-48.04 75.03,-48.04 67.48,-55.59 67.48,-60.44 72.47,-65.44 72.43,-65.47 X5.B6
  Bottom 1.778: 90.92,10.11 F3.2
N$17
  Top 0.61: 35.24,58.76 K6.1 | 31.88,64.21 31.88,64.33
  Top 1.676: R6.2 18.98,67.58 28.51,67.58 31.88,64.21 35.24,60.84 35.24,58.76 | 31.88,64.33 L6.1
N$18
  Bottom 1.676: 24.67,71.83 24.69,71.84 24.43,71.84 C6.2 24.41,71.87 24.46,71.92 22.22,74.16 R6.1
N$19
  Bottom 1.778: F5.2 71.84,51.19 79.47,58.82 X6.B2
N$20
  Bottom 1.676: F8.2 -12.74,96.67 -1.1,96.08 | 20.62,98.01 31.65,93.62 32.1,90.03 40.41,86.66 44.22,88.68 54.1,83.74 56.8,81.05
  Bottom 1.778: -1.1,96.08 14.48,95.9 20.62,98.01 | 56.8,81.05 X6.B8
N$21
  Bottom 1.676: C7.2 -4.15,75.21 -6.32,75.21 R7.1
N$22
  Top 1.676: R7.2 -7.19,67.16 -7.19,70.5 -6.74,70.95 6.28,70.95 | 6.28,70.95 8.08,70.95 11.22,67.8 11.22,66.97 | 11.22,66.97 11.22,66.91 | 11.22,66.97 K7.1 | L7.1 6.06,76.78 6.06,71.62 6.28,71.39 6.28,70.95
N$23
  Top 1.676: R8.2 -30.31,59.25 -30.31,62.19 -27.62,64.89 -23.13,66.46 -22.79,66.79 | -22.79,66.79 -22.23,67.35 -21.11,78.78 L8.1 | -22.79,66.79 -22.68,66.68 -15.56,66.68 K8.1
N$24
  Bottom 1.676: C8.2 -30.99,66.5 -30.99,66.46 -33.66,66.46 R8.1
N$25
  Bottom 1.676: 22,93.85 28.06,91.83 29.41,86.44 40.41,81.72 44.9,84.87 50.78,81.87 49.14,74.73 56.53,67.34 59.81,67.34 61.92,69.44 61.92,69.66 65.1,72.84 65.22,72.84 | 65.22,72.84 65.24,72.84 | 65.22,72.84 X6.B6
  Bottom 1.778: F7.2 17.51,92.05 22,93.85
N$26
  Bottom 1.676: F6.2 44.51,73.76 58.39,59.88 66.32,59.88 72.13,65.68 72.16,65.66 X6.B4
N$27
  Bottom 1.016: R112.2 68.47,-18.63 67.12,-18.63 66.9,-18.41 66.81,-18.5 K2.3
N$28
  Bottom 1.016: K3.3 67.39,3.1 67.35,3.15 67.62,3.42 R113.2
N$29
  Bottom 1.016: K4.3 61.99,25.56 61.96,25.6 63.41,27.04 R114.2
N$30
  Bottom 0.813: K5.3 37.49,35.74 37.49,36.6 38.83,37.94 38.83,37.87 R115.2
N$31
  Bottom 0.813: K6.3 23.34,63.76 23.34,64.55 R116.2
N$32
  Bottom 0.813: K7.3 -1.34,67.34 -1.76,67.76 R117.2
N$33
  Bottom 0.813: R118.2 | R118.2 | K8.3 -25.75,61.67 R118.2
N$34
  Bottom 1.016: R119.2 39.28,-37.94 K1.3
N$36
  Bottom 1.016: R101.2 -67.96,22.61 -66.46,22 -66.01,22 -65.75,22.26 K10.3
N$38
  Bottom 0.305: R111.2 -71.85,-3.14 -69.83,-3.14 K11.3
N$40
  Bottom 1.016: K12.3 -63.22,-27.49 -63.09,-27.61 -63.85,-28.37 R121.2
N$42
  Bottom 0.813: R131.2 -37.05,-39.73 K13.3
N$44
  Bottom 0.813: R141.2 -21.84,-66.28 -22.01,-66 -21.33,-63.98 -21.36,-64.01 K14.3
N$46
  Bottom 1.016: K15.3 2.5,-67.09 2.46,-67.12 2.83,-67.5 151.2
N$48
  Bottom 0.813: K16.3 24.03,-61.75 25.36,-63.08 R161.2
N$50
  Bottom 1.016: R91.2 -41.31,35.47 K9.3
N$59
  Bottom 1.676: R9.1 -44.39,30.09 -42.84,30.31 -31.62,41.53 -31.62,44.52 -31.92,44.82 -31.89,44.85 K9.1 -31.89,45.22 -31.84,45.26 -31.88,45.3 -31.88,49.11 -39.12,56.35 L9.1
N$60
  Bottom 1.676: R9.2 -52.87,38.39 -49.62,38.39 -48.27,39.74 -48.27,39.87 C9.2
N$61
  Bottom 1.676: K10.1 -60.62,34.13 -67.81,41.31 -73.19,41.31 -74.94,39.57 L10.1 -75.22,39.52 -75.22,32.56 -71.4,28.74 -71.4,18.98 R10.2
N$62
  Bottom 1.676: R10.1 -79.56,20.29 -79.48,20.21 -76.56,23.13 -74.3,23.13 C10.2
N$63
  Bottom 1.676: R11.2 -70.11,-9.82 -77.46,-2.47 -77.46,2.02 | L11.1 -77.81,2.02 -77.46,2.02 | K11.1 -69.88,9.88 -70.05,9.88 -70.05,9.43 -77.46,2.02
N$64
  Bottom 1.676: -79.92,-9.86 -79.93,-9.88 | -79.92,-9.86 R11.1 | C11.2 -78.45,-8.4 -79.92,-9.86
N$65
  Bottom 1.676: -69.64,-33.26 -69.6,-33.23 | C12.2 -69.64,-33.26 | R12.1 -71,-34.62 -69.64,-33.26
N$66
  Bottom 1.676: R12.2 -64.31,-34.03 -71.4,-26.94 | -82.48,-22.14 L12.1 -77.45,-27.16 -71.62,-27.16 -71.4,-26.94 | K12.1 -68.1,-16.01 -71.4,-19.3 -71.4,-26.94
N$67
  Bottom 1.676: K13.1 -46.48,-29.86 -50.52,-29.86 -55.01,-34.35 -55.01,-37.49 -44.68,-47.82 L13.1 -43.78,-52.76 R13.2
N$68
  Bottom 1.676: C13.2 -34.27,-46.38 R13.1
N$69
  Bottom 1.676: K14.1 -31.89,-60.42 -31.89,-73.19 -24.93,-80.15 | -24.93,-80.15 -24.91,-80.15 L14.1 | R14.2 -23.34,-80.15 -24.93,-80.15
N$70
  Bottom 1.676: C14.2 -22.22,-72.06 -17.29,-72.06 -16.17,-70.94 -16.01,-70.94 R14.1
  Bottom 1.778: R14.1 -15.95,-70.72
N$71
  Bottom 1.676: 9.42,-70.69 9.42,-70.49 | R15.1 9.42,-70.69 | 4.93,-75.88 9.42,-71.39 9.42,-70.69
  Bottom 1.778: 4.93,-75.88 C15.2
N$72
  Bottom 1.676: 5.16,-82.83 5.16,-82.84 | 5.16,-82.83 L15.1 5.37,-82.62 8.65,-82.62 R15.2 | K15.1 5.16,-82.3 5.16,-82.83
N$73
  Bottom 1.676: K16.1 15.84,-70.04 20.65,-70.04 25.36,-74.76 32.1,-74.76 32.1,-74.71 L16.1 | 31.88,-74.53 31.92,-74.53 L16.1 | R16.2 37.05,-74.31 32.1,-74.31 32.1,-74.55 L16.1
N$74
  Bottom 1.676: 32.32,-62.71 32.32,-62.41 | R16.1 32.32,-62.71 | 29.85,-68.02 32.32,-65.55 32.32,-62.71
  Bottom 1.778: 29.85,-68.02 C16.2
N$75  (via drill 0.7)
  Top 0.406: C17.1 -10.47,-39.94 -9.78,-40.64 -6.22,-40.64 v-5.71,-40.01 -5.4,-39.69 R17.1
  Bottom 0.406: U$1.2 1.27,-35.4 0.16,-35.4 -3.05,-38.61 | -3.05,-38.61 -3.08,-38.64 | -3.05,-38.61 | v-5.71,-40.01 -4.45,-40.01 -3.05,-38.61
N$79
  Top 0.406: U$2.3 -10.63,-30.32 -12.22,-28.73 -15.56,-28.73 -15.88,-29.05 -15.88,-30.8 -15.87,-30.8 | -15.87,-30.8 C19.2 | R22.2 R21.1 | -15.87,-30.8 R22.2 | R22.2 -15.72,-33.97 | R21.1 -16.03,-37.62 | R21.1
N$80
  Top 0.406: -8.41,-39.05 | -8.41,-39.05 C17.2 | R20.2 -8.57,-38.89 -8.41,-39.05
N$81
  Top 0.406: -2.7,-32.7 | R23.2 -2.7,-32.7 | -2.7,-32.7 C18.1 -5.87,-32.07 -9.05,-32.07 -10.35,-33.37 U$2.4 -10.63,-33.34 | -2.7,-32.7 | -10.63,-33.34 -10.64,-33.34 | R20.1 -10.47,-33.5 -10.63,-33.34
N$139
  Bottom 1.676: F12.2 -91.38,-21.28 -91.38,-21.33 -91.38,-19.53 -99.24,-11.67 -99.24,-9.43 -93.85,-4.49 -94.07,6.96 -99.46,11 -99.46,19.98 -99.24,20.21 -94.75,30.98 -90.71,31.88 -87.56,39.07 -90.26,42.66 -85.99,53.21 -85.99,53.84 -82.31,57.51 | -82.3,57.53 -82.31,57.51 | -82.31,57.51 X2.B8
  Bottom 1.778: -91.38,-21.33 F12.2
N$140
  Bottom 1.778: F9.2 -46.93,64.44 -61.3,78.8 X2.B2
N$141
  Bottom 1.676: F10.2 -80.82,42.66 -75.89,42.66 -59.05,59.5 -59.05,62.64 -68.25,71.84 -68.25,71.72 X2.B4
N$142
  Bottom 1.676: -93.4,13.47 -95.42,15.49 -95.42,21.33 -93.4,27.39 -87.79,28.07 -83.3,39.29 -87.34,42.43 -84.19,49.17
  Bottom 1.778: X2.B6 -67.81,57.03 -68.03,55.01 -72.07,50.97 -80.83,48.05 -84.19,49.17 | -93.4,13.47 F11.2
N$143
  Bottom 1.676: F13.2 -56.13,-51.63 -70.72,-51.41 -79.02,-59.71 X3.B2
N$144
  Bottom 1.676: -50.59,-86.44 -46.1,-88.23 -41.87,-89.36 -38.2,-87.26 -31.66,-90.03 -29.31,-95.75 -23.13,-98.11 | -15.27,-98.33 -6.83,-98.13 -3.11,-93.92 5.32,-94.13 13.88,-97.56 13.91,-97.43
  Bottom 1.778: -50.59,-86.44 X3.B8 | -15.27,-98.33 -23.13,-98.11 | 13.91,-97.43 38.61,-86.21 40.41,-79.47 F16.2
N$145
  Bottom 1.676: -47.15,-84.41 -42.78,-85.92 -38.98,-83.39 -28.86,-87.74 -26.27,-93.62 -22.68,-94.96 | -14.82,-95.19 -9.65,-95.02 -5.43,-90.24 9.81,-90.56 F15.2
  Bottom 1.778: X3.B6 -59.05,-68.02 -56.36,-68.02 -46.48,-77.9 -47.15,-84.41 | -14.82,-95.19 -22.68,-94.96 | F15.2 9.42,-90.7
N$146
  Bottom 1.676: X3.B4 -72.09,-66.69 -65.78,-60.39 -56.36,-60.39 -49.4,-67.35 -41.76,-67.35 -35.48,-73.64 -35.48,-76.78 -22.68,-89.58 -22.67,-89.58 F14.2 -22.45,-89.81
  Bottom 1.778: F14.2 -22.23,-89.58
N$163
  Bottom 0.61: R64.1 -25.3,-15.48 -25.29,-15.48 -25.29,-13.76 LED33.A
RES
  Bottom 0.61: JP10.1 -23.41,-25.8 -23.35,-25.8 -23.35,-22.89 | R65.1 -23.35,-19.68 -23.35,-22.89 | -36.01,-17.6 -36.16,-17.6 | -36.01,-17.6 S1.3 | -36.01,-17.6 -29.51,-17.6 S1.4 -24.21,-22.89 -23.35,-22.89
RX0
  Bottom 0.305: SV3.1 -12.38,10.97
  Bottom 0.406: -3.37,19.98 4.85,20.01 6.98,22.14 6.98,22.37 JP4.1
  Bottom 0.61: -12.38,10.97 -3.37,19.98
RX3V3
  Top 0.406: R19.1 12.57,32.89 | R19.1 | R18.2 11.18,32.86 | 11.18,32.86 R19.1 | JP2.2 17.78,29.72 16.89,28.83 11.94,28.83 11.18,29.72 11.18,32.86 | 11.18,32.86 11.05,32.89
SCL
  Bottom 0.406: SV4.1 10.23,11.23 18.4,11.23 29.41,22.23 29.41,22.45 29.29,22.45 JP5.8
SDA
  Bottom 0.305: 26.7,21.32 JP5.7 | 8.08,6.74 8.04,6.71 SV4.3
  Bottom 0.406: 26.7,21.32 17.73,12.35 8.3,12.35 5.61,9.66 5.61,9.21 8.08,6.74
TX1
  Bottom 0.305: SV3.3 -11.12,9.05 -11.12,11.12 -10,12.24 -9.32,12.24
  Bottom 0.406: -9.32,12.24 -2.59,18.97 -2.58,18.96 5.3,18.96 6.95,20.61 8.52,20.61 9.26,21.35 9.26,23.6 8.52,24.34 5.61,24.34 4.51,23.24 4.51,22.44 JP4.2
TX3V3
  Top 0.406: Q1.2 17.78,36.32 17.78,35.56 17.27,35.05 8.76,35.05 7.62,36.2 7.62,38.48 8.19,39.05 R24.2 | Q1.2 17.7,36.24 17.65,36.2 17.78,36.07 | Q1.2 17.44,36.24 17.53,36.32 19.18,36.32 19.43,36.07 19.43,31.88 20.32,30.99 JP2.3
VCC  (via drill 0.6, 0.8)  (1 unrouted)
  Top 0.406: U$2.5 -8.73,-33.34 -5.87,-36.2 R17.2 -5.24,-36.2 -4.6,-36.2 -3.49,-37.31 -3.49,-39.37 -5.56,-41.43 -10.64,-41.43 -13.97,-38.1 R21.2 -14.13,-37.62 -13.97,-37.78 -13.97,-39.69 -14.29,-40.01 v-14.45,-40.01
  Top 0.61: 55.09,-23.5 55.06,-23.52 SV6.14 55.04,-23.61 55.09,-23.65 55.09,-25.4 53.82,-26.67 50.96,-26.67 48.58,-24.29 48.58,-23.65 36.83,-23.65 33.81,-20.64 33.81,-11.15 28.36,-5.7 | SV7.14 55.03,2.8 55.24,3.02 56.36,3.02 58.26,4.92 58.26,19.68 55.54,22.41 JP12.2 40.36,22.44 40.33,22.41 JP12.1 37.47,22.5 37.45,22.52 37.49,22.56 37.49,31.13 28.84,39.37 20.07,39.37 v20.1,39.34 | 14.92,39.21 | 14.92,39.21 R25.1 | 28.36,-5.7 28.31,-5.65 | SV5.14 28.36,-5.7 | 14.92,39.21 14.92,39.31 15.62,40.01 19.56,40.01 20.19,39.37 20.16,39.34 v20.1,39.34 | v20.1,39.34
  Top 0.813: SV7.14 57.92,-0.09 57.92,-20.65 55.11,-23.46 55.1,-23.46 SV6.14
  Bottom 0.305: 14.55,-8.72 14.55,-20.61
  Bottom 0.406: 14.55,-20.61 14.5,-20.67 14.5,-21.35 13.43,-22.42 12.45,-22.42 12.45,-22.47 R66.1 | JP10.3 -18.38,-38.77 -17.14,-40.01 v-14.45,-40.01 | v20.1,39.34 20.16,39.34 20.19,39.37 20.24,39.32 C99.+
  Bottom 0.61: 26.89,-8.62 26.99,-8.52 27.45,-8.52 28.36,-7.62 SV5.14 | -20.79,-8.84 -20.8,-8.85 -20.8,-23.44 JP10.3 | 14.55,-8.72 14.55,-8.65 12.1,-6.19 SV4.14 10.51,-6.12 | 10.51,-6.12 10.51,-6.03 | 10.51,-6.12 10.51,-7.46 9.95,-8.01 -7.12,-8.01 -8.09,-7.04 -9.88,-7.04 -9.96,-7.04 | C99.+ 20.24,35 | R55.2 12.92,42 14.92,40.01 19.56,40.01 20.1,39.47 v20.1,39.34 | SV5.14 28.38,-5.77 | SV5.14 | v20.1,39.34 20.07,39.37 | v20.1,39.34 | v20.1,39.34 20.24,39.19
  Bottom 0.813: SV2.14 -28.56,-5.57 -25.37,-8.75 -20.79,-8.84 -13.48,-8.98 -11.68,-8.98 -9.88,-7.18 -9.88,-7.04 -9.88,-4.94 -9.86,-4.92 SV3.14 | 14.55,-8.72 26.89,-8.62 | SV6.14 55.04,-23.53 | 10.32,-8.53
(copper drawn outside any net)
  shapes: Bottom circle x1, Top circle x1

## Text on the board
tNames: L9 | B | L8 | L10 | L7 | L11 | L6 | L12 | L5 | C | GND | TX5V | RX5V | GND | RX3V3 | TX3V3 | ~AC2 | ~AC1 | INPUT1 | OUTPUT5 | OUTPUT1 | OUTPUT2 | OUTPUT3 | OUTPUT4 | INPUT2 | OUTPUT6 | POT1 | POT2 | POT3 | T1 | T2 | S1 | DISKO3200 (rev.b) / 2011 | designed by nakednindza | nakednindza@pravi.me | A | L13 | L4 | L14 | L3 | L15 | L2 | L16 | D | L1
